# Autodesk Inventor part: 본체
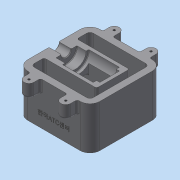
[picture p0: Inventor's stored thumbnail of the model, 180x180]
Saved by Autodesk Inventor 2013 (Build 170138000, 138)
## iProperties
Created: 2018-01
Part Number: 본체
Material: 일반
Document SubType Name: Modeling
Designer: dgall
Density: 1 g/cm^3
Author: dgall
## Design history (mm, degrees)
sketch "스케치1"
  geometry: L1 (0, 0)-(110, 0); L2 (110, 0)-(110, 110); L3 (110, 110)-(0, 110); L4 (0, 110)-(0, 0)
  constraints: 8 end point, 2 parallel, 1 horizontal, 1 perpendicular
  dimensions: "d0" = 110 distance between parallel lines of L2 L4; "d2" = 110 distance between parallel lines of L1 L3
extrude "돌출1" new body sketch "스케치1" distance "d3" = 65; taper "d4" = 0 deg
sketch "스케치2"
  geometry: L1 (110, 110)-(0, 110) reference; L2 (0, 110)-(0, 0) reference; L3 (19.5, 120)-(19.5, 110); L4 (34.5, 120)-(34.5, 110); A1 r 7.5 centre (27, 120) between (34.5, 120) and (19.5, 120)
  constraints: 4 end point, 2 point on circle, 2 point on line, 2 tangent, 1 centre point, 1 parallel, 1 perpendicular
  dimensions: "d6" = 7.5 radius of A1; "d7" = 10 distance from line of A1.centre L1; "d8" = 27 distance from line of A1.centre L2
extrude "돌출2" join sketch "스케치2" distance "d9" = 20; taper "d10" = 0 deg
hole "구멍1" diameter "d13" = 3.242; stored, may be unused: countersink angle "d17" = 90 deg, drill point angle "d19" = 118 deg; dims "d11" = 10, "d12" = 10, "d14" = 9, "d15" = 4, "d16" = 2, "d18" = 11
node "작업 평면1"
fillet "모깎기1" dims "d23" = 15
sketch "스케치3"
  geometry: L1 (0, 0)-(85, 0); L2 (0, 0)-(0, -7.5); L3 (0, -7.5)-(19, -7.5); L4 (19, -7.5)-(19, -16); L5 (19, -16)-(33, -16); L6 (33, -16)-(33, -20); L7 (33, -20)-(80, -20); L8 (80, -20)-(80, -15); L9 (80, -15)-(85, -15); L10 (85, -15)-(85, 0)
  constraints: 20 end point, 7 parallel, 2 perpendicular, 1 horizontal
  dimensions: "d25" = 15 diameter of L3 L1; "d26" = 32 diameter of L5 L1; "d27" = 40 diameter of L7 L1; "d28" = 30 diameter of L9 L1; "d29" = 19 distance between parallel lines of L4 L2; "d30" = 14 distance between parallel lines of L6 L4; "d31" = 47 distance between parallel lines of L8 L6; "d32" = 5 distance between parallel lines of L10 L8
revolve "회전1" sketch "스케치3" stored, may be unused: angle "d33" = 90 deg
sketch "스케치4"
  geometry: L1 (34.5, 0)-(75.5, 0) reference; L2 (110, 15)-(110, 95) reference; L3 (75.5, 110)-(34.5, 110) reference; L4 (0, 95)-(0, 62.5) reference; L5 (0, 47.5)-(0, 62.5) reference; L6 (90, 80)-(90, 30); L7 (90, 30)-(10, 30); L8 (10, 30)-(10, 10); L9 (10, 10)-(100, 10); L10 (100, 10)-(100, 100); L11 (100, 100)-(10, 100); L12 (10, 100)-(10, 80); L13 (10, 80)-(90, 80); 4 further points
  constraints: 16 end point, 4 parallel, 3 midpoint, 2 perpendicular, 1 collinear, 1 horizontal alignment, 1 vertical alignment
  dimensions: "d36" = 20 distance between parallel lines of L2 L6; "d38" = 30 distance between parallel lines of L13 L3; "d39" = 10 distance between parallel lines of L9 L1; "d41" = 10 distance between parallel lines of L3 L11; "d42" = 10 distance between parallel lines of L12 L4; "d43" = 10 distance between parallel lines of L2 L10
extrude "돌출3" cut sketch "스케치4" stored distance "d44" = 20; taper "d45" = 0 deg
fillet "모깎기2" dims "d46" = 5
sketch "스케치5"
  geometry: L1 (100, -65)-(100, 0) reference; L2 (100, 0)-(110, 0) reference; L3 (110, 0)-(110, -65) reference; L4 (110, -65)-(100, -65) reference; L5 (0, -7.5)-(19, -7.5) reference; L6 (19, -7.5)-(19, -16) reference; L7 (19, -16)-(33, -16) reference; L8 (33, -16)-(33, -20) reference; L9 (33, -20)-(80, -20) reference; L10 (80, -20)-(80, -15) reference; L11 (80, -15)-(85, -15) reference; L12 (85, -15)-(85, 0) reference; L13 (85, 0)-(90, 0) reference; L14 (90, 0)-(90, -65) reference; L15 (90, -65)-(0, -65) reference; L16 (0, -65)-(0, -7.5) reference; L17 (10, -65)-(10, -56.436); L18 (10, -56.436)-(90, -35); L19 (0, -35.939)-(38, -25.757); L20 (38, -25.757)-(38, -20); L21 (75, -20)-(75, -33.843); L22 (75, -33.843)-(0, -53.939); 1 further point
  constraints: 12 end point, 6 point on line, 3 parallel, 1 perpendicular
  dimensions: "d47" = 105 deg angle of L18 L17; "d50" = 30 distance from line of L18.end L15; "d51" = 10 distance between parallel lines of L17 L16; "d64" = 5 distance between parallel lines of L22 L18; "d65" = 5 distance between parallel lines of L10 L21; "d66" = 37 distance between parallel lines of L20 L21; "d67" = 18 distance of L19.start L22.end
  node "절단 모서리 투영1"
extrude "돌출4" cut sketch "스케치5" stored distance "d55" = 50; taper "d56" = 0 deg
extrude "돌출6" cut sketch "스케치5" stored distance "d68" = 30; taper "d69" = 0 deg
sketch "스케치7"
  geometry: L1 (100, 95)-(100, 15) reference; L2 (80, 40)-(80, 35) reference; L3 (33, 35)-(33, 39) reference; L4 (38, 70)-(75, 70); L5 (75, 70)-(75, 40); L6 (75, 40)-(38, 40); L7 (38, 40)-(38, 70); 3 further points
  constraints: 8 end point, 2 midpoint, 2 parallel, 1 horizontal, 1 horizontal alignment, 1 perpendicular
  dimensions: "d70" = 5 distance between parallel lines of L7 L3; "d71" = 5 distance between parallel lines of L2 L5; "d72" = 30 distance between parallel lines of L4 L6
extrude "돌출7" cut sketch "스케치7" stored distance "d73" = 80; taper "d74" = 0 deg
chamfer "모따기1" distance "d75" = 1; stored, may be unused: second distance "d76" = 2, angle "d77" = 45 deg
fillet "모깎기3" dims "d78" = 1
sketch "스케치8" dims "d0" = 110, "d2" = 110
  geometry: L1 (60.5, -65)-(-19.5, -65) reference; L2 (-34.5, 0)-(-34.5, -65) reference; 1 further point
  constraints: 1 other
  dimensions: "d79" = 55 distance from line of point (20.5, -45) L2; "d80" = 20 distance from line of point (20.5, -45) L1
feature "엠보싱1" sketch "스케치8" dims "d0" = 110, "d2" = 110, "d81" = 0.5, "d82" = 0
fillet "모깎기4" dims "d83" = 3
fillet "모깎기5" dims "d84" = 3
fillet "모깎기6" dims "d85" = 3
fillet "모깎기7" dims "d86" = 3
node "솔리드1"
pattern_linear "직사각형 패턴1" dims "d22" = 56
mirror "대칭1"
